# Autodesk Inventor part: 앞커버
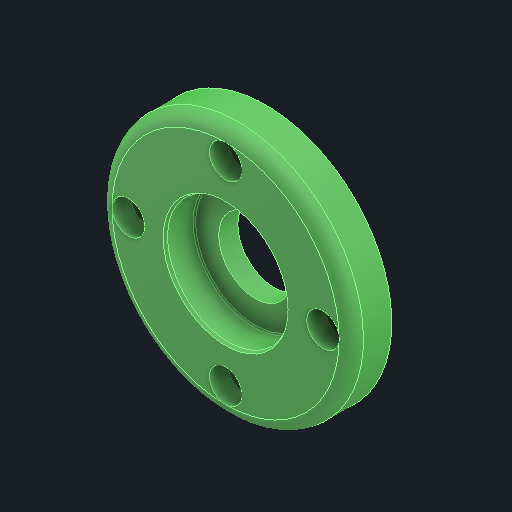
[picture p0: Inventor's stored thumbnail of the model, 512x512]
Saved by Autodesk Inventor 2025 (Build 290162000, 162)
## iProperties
Created: 2025-08
Part Number: 앞커버
Material: 알루미늄 6061
Document SubType Name: Modeling
Designer: infra10
Density: 2.71 g/cm^3
Appearance: 기본값
Author: jhkim
Sending System: Autodesk Inventor 2026
Preprocessor: ST-DEVELOPER v20.1
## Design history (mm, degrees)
feature "솔리드1"
node "솔리드2"
